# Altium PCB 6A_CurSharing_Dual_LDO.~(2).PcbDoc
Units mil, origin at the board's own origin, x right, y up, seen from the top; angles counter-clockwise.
Board outline 3000 x 2000 mil, 4 copper layers (Top Layer, MidLayer1, MidLayer2, Bottom Layer), stack 90 mil thick; 43 components, 16 nets, 118 pads, 82 vias.
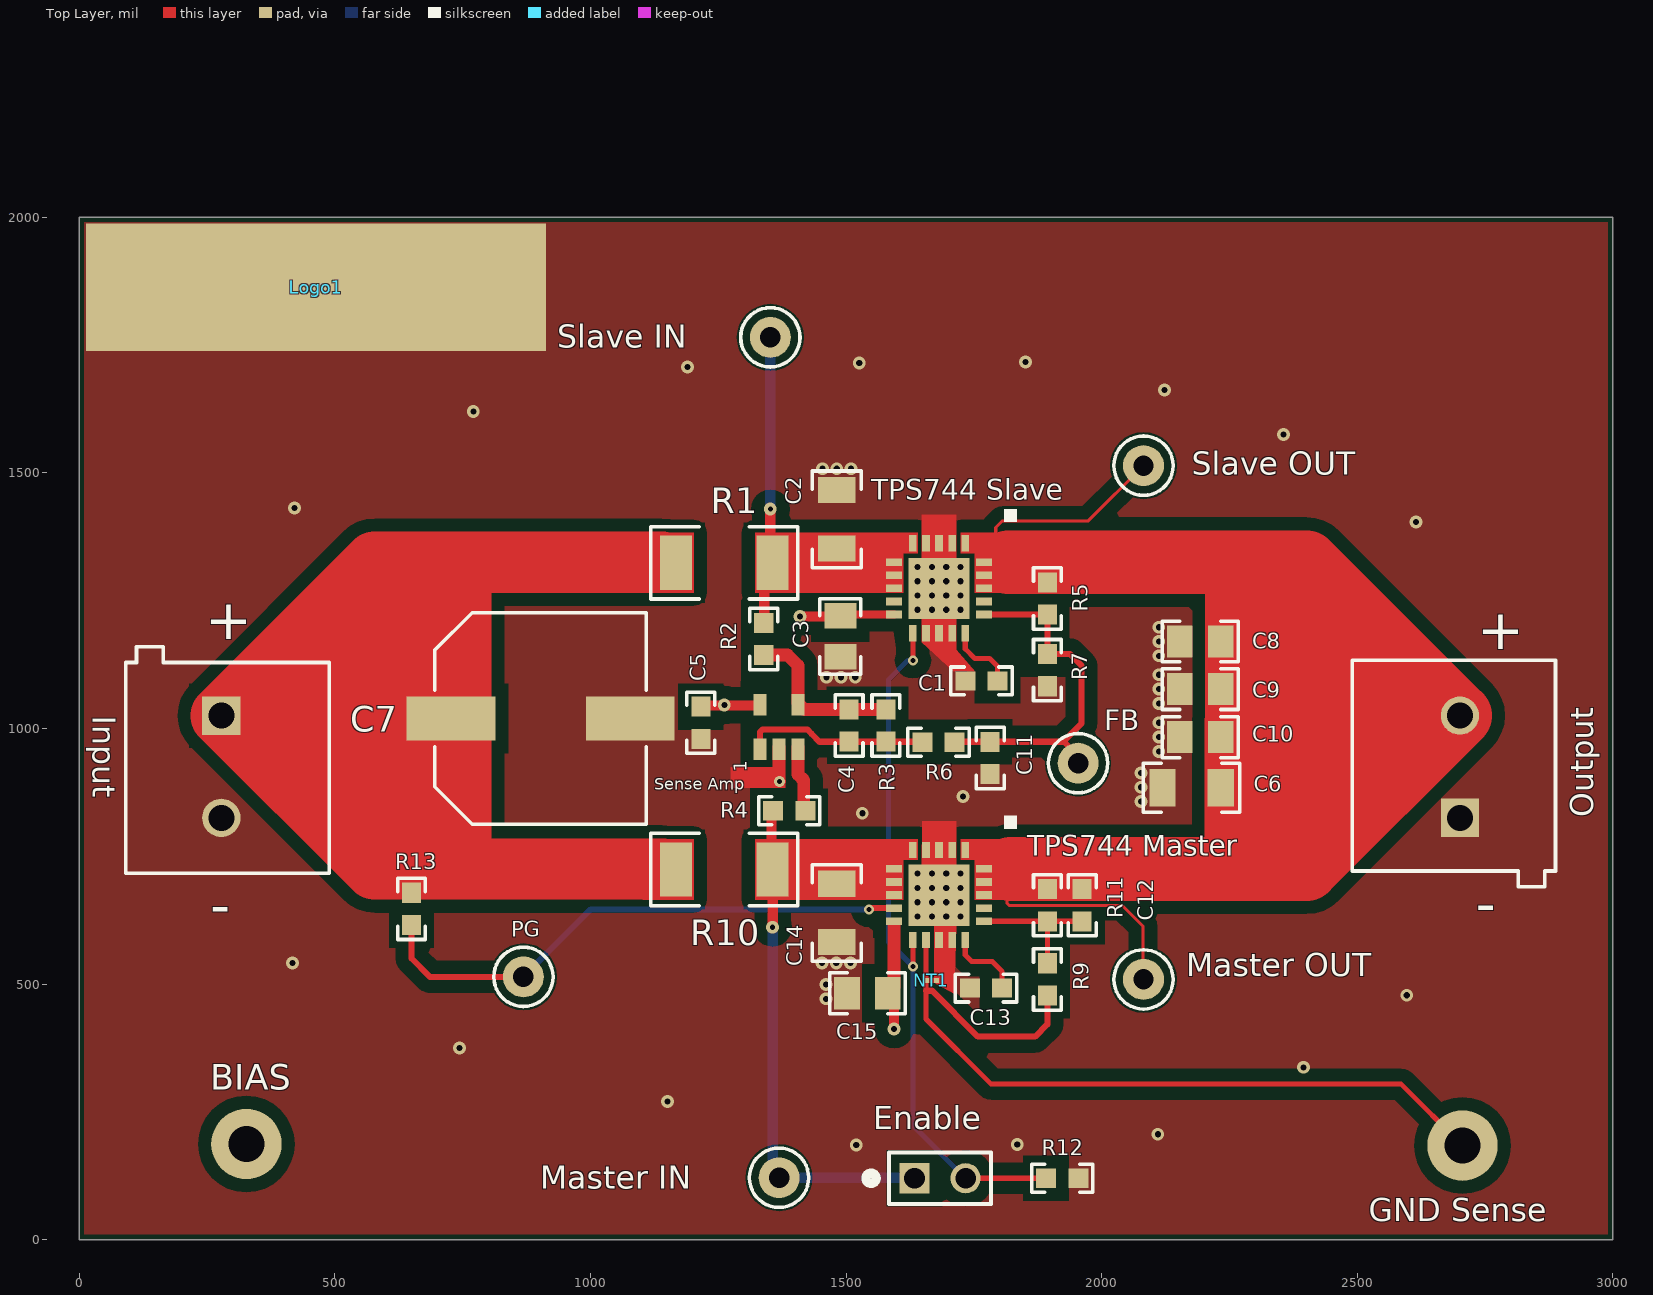
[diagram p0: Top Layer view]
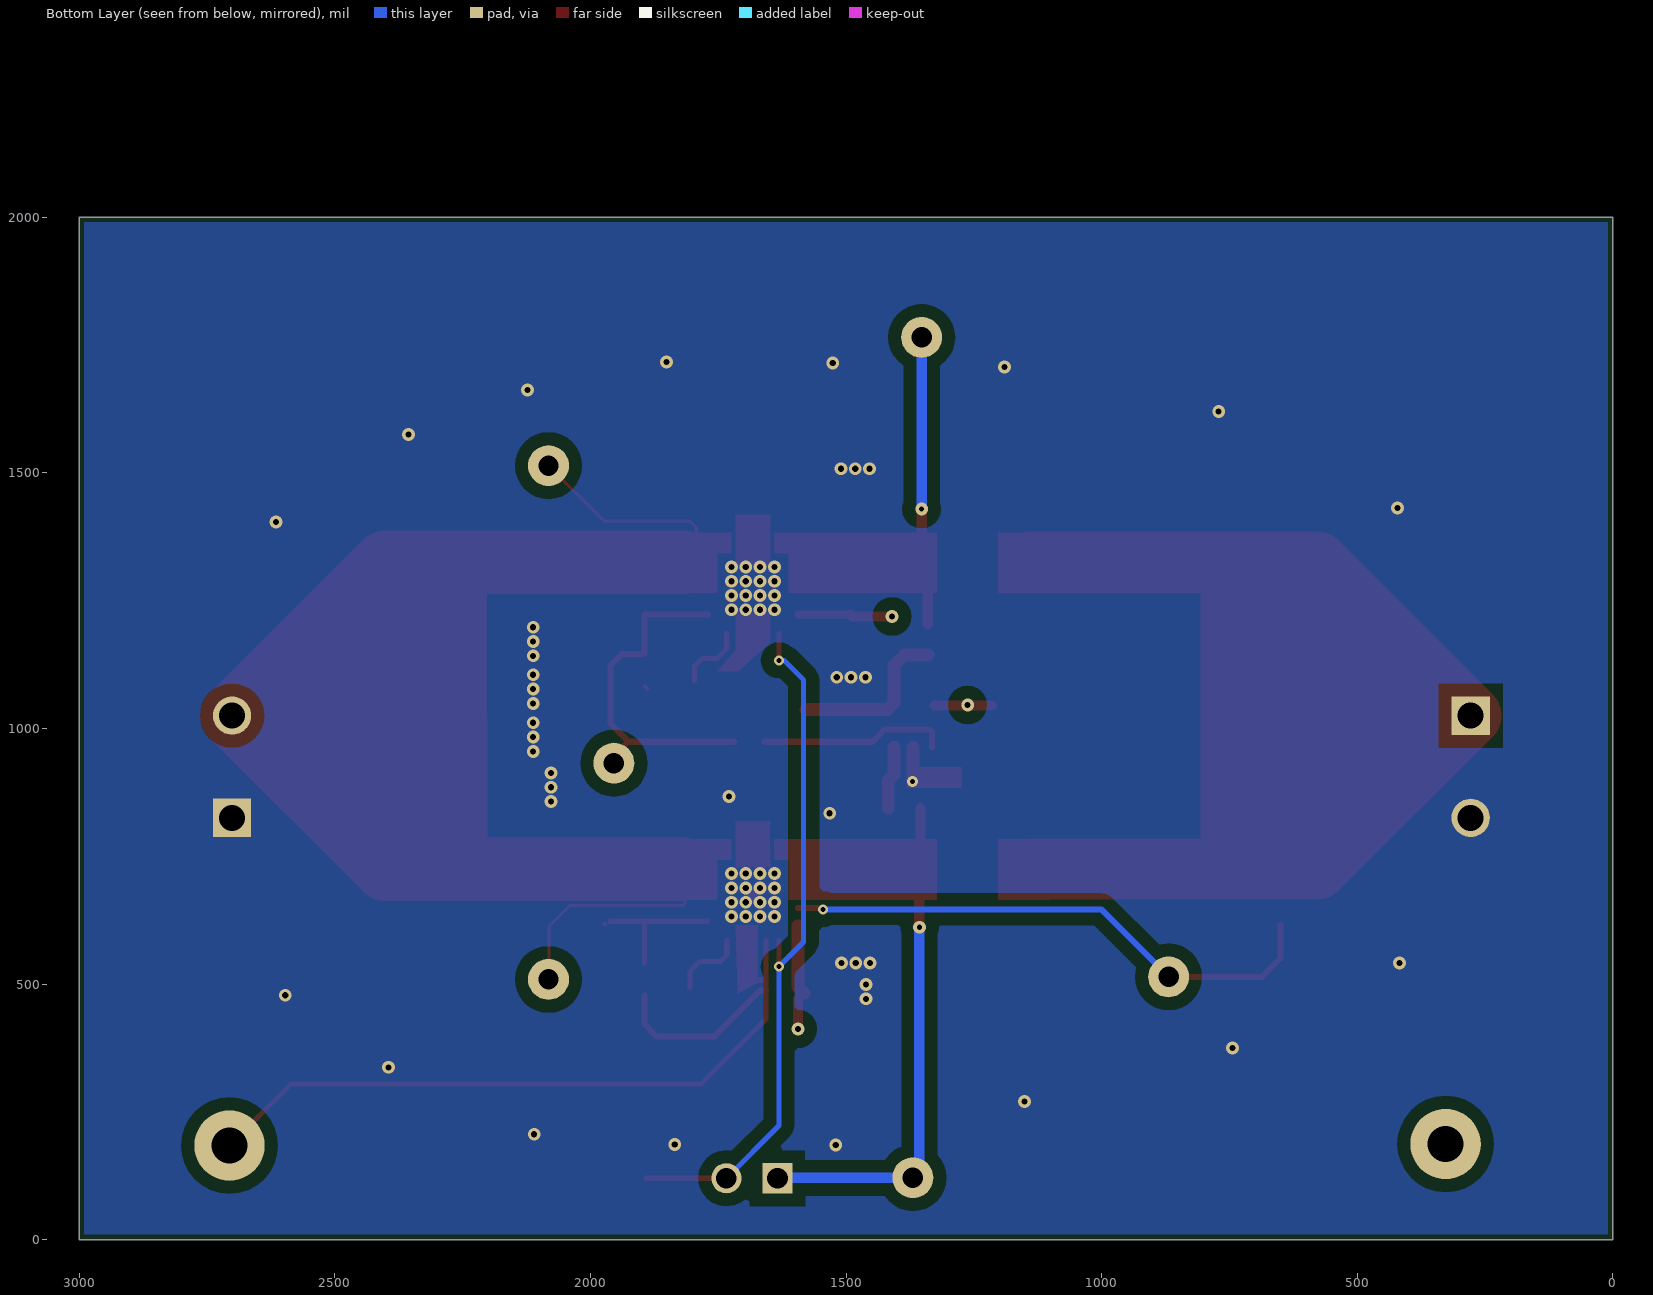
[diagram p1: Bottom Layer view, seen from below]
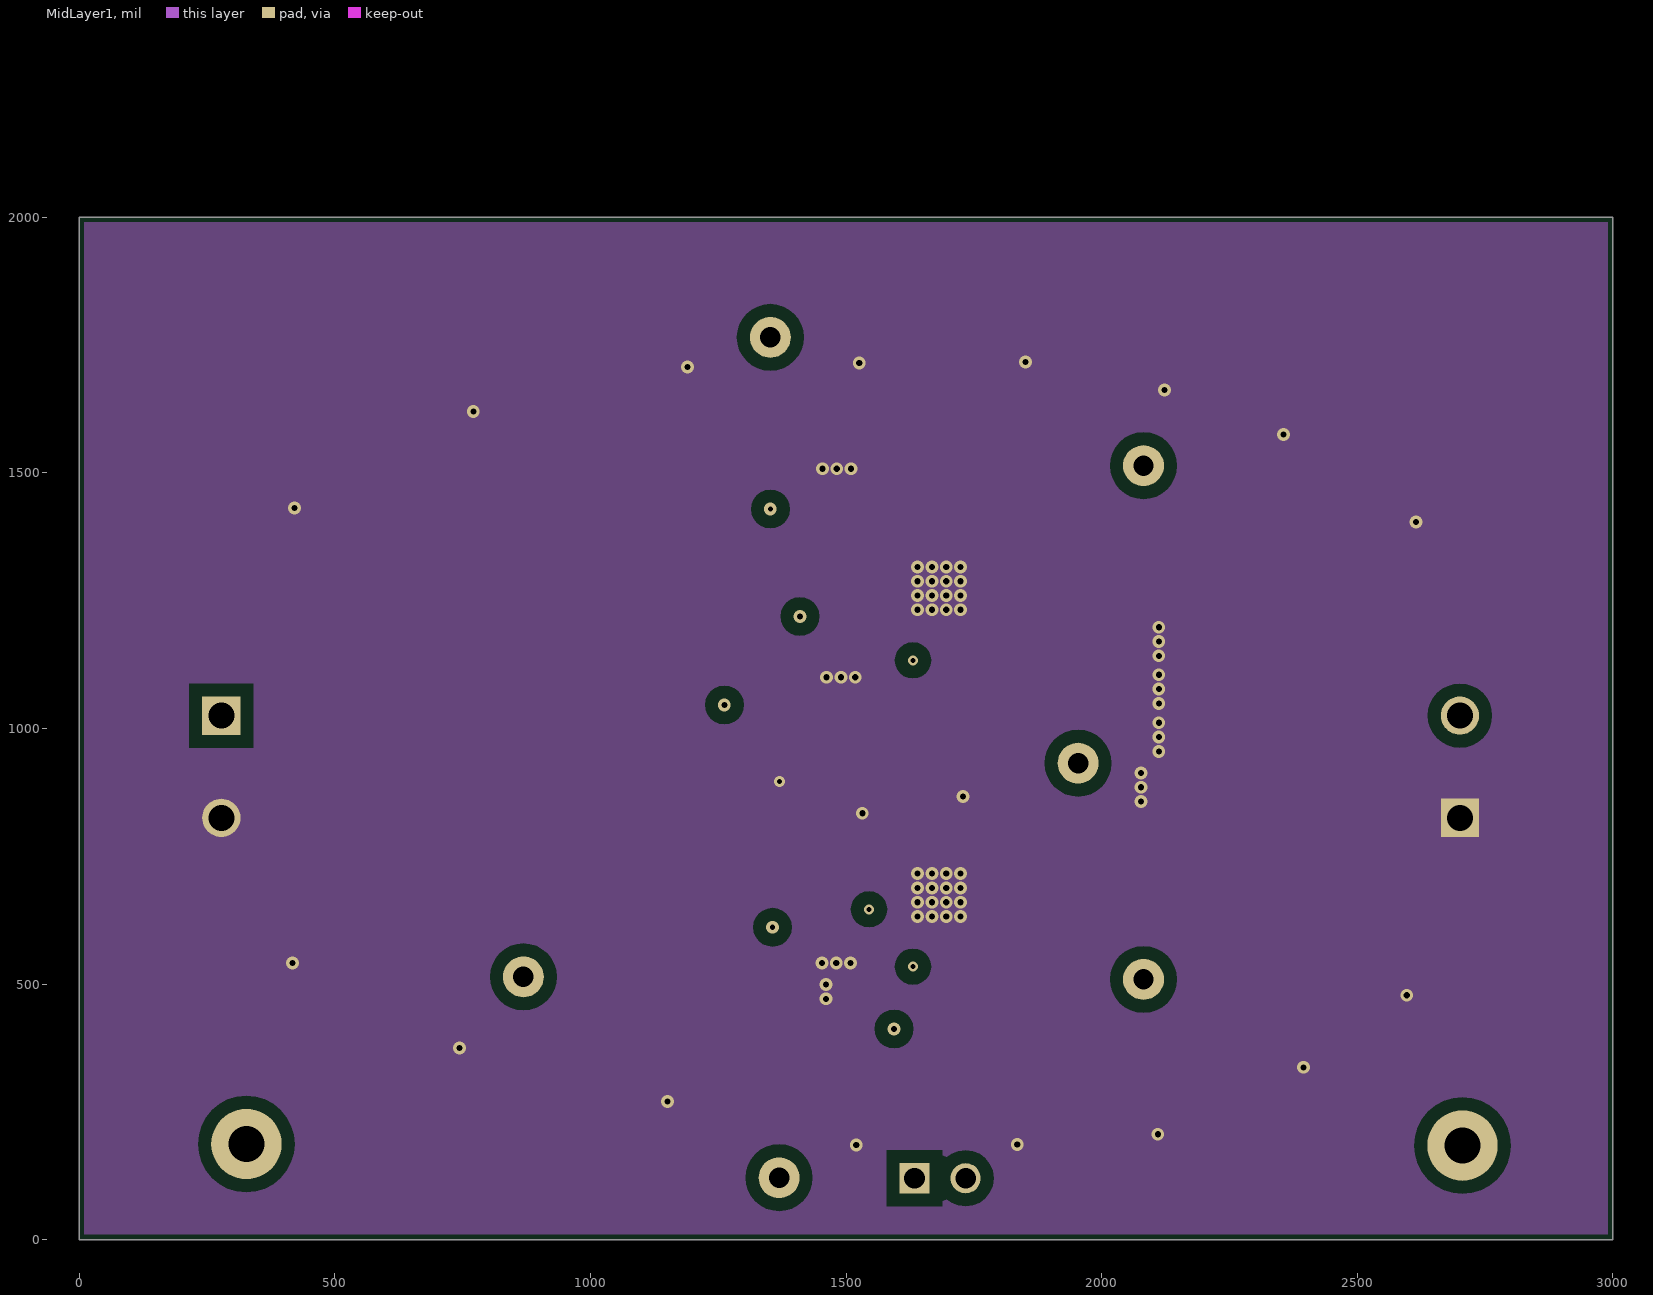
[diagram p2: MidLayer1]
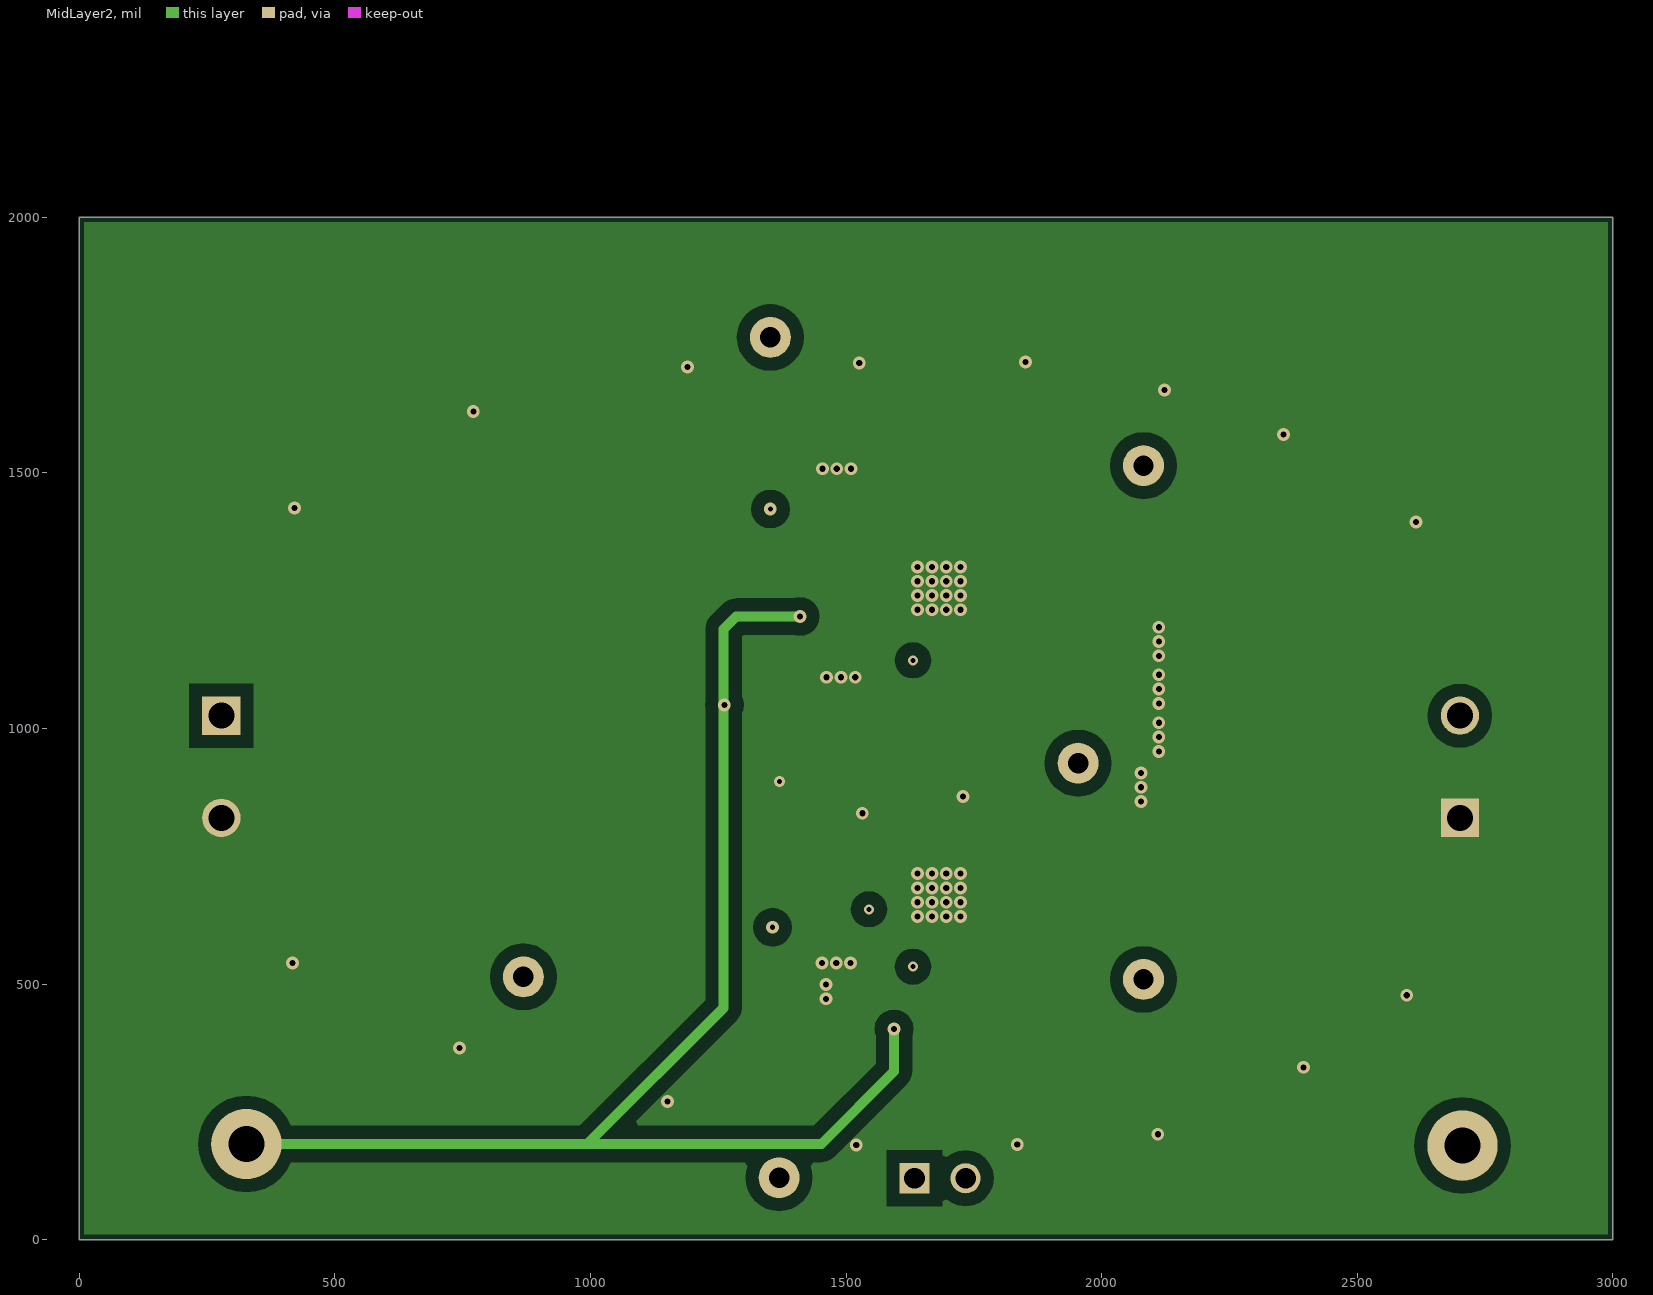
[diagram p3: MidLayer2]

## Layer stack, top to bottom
Top Layer: signal copper 1.4
Dielectric: core 59.2, FR-4, Dk 4.8
MidLayer1: signal copper 1.4
Dielectric: prepreg 12.6, FR-4, Dk 4.8
MidLayer2: signal copper 1.4
Dielectric: core 12.6, FR-4, Dk 4.8
Bottom Layer: signal copper 1.4

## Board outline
0,0 3000,0 3000,2000 0,2000

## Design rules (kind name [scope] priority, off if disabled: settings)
AcuteAngle [All] p1: minimum=4.50000000000000E+0001 checktracksonly=FALSE
AssemblyTestPointUsage [All] p1: valid=2
Clearance Clearance_BoardEdge_MountingHoles [OnCopper and InComponentClass('Mounting Holes') vs IsKeepOut] p1: gap=40
Clearance Clearance_BoardEdge_Poly [OnCopper and InPoly vs IsKeepOut] p2: gap=25
Clearance Clearance_BoardEdge [OnCopper and Not InComponentClass('Logo') and not InComponentClass('FiducialMark') and not InRegion(1000,500,4000,800) and Not IsKeepout vs IsKeepOut] p3: gap=75
Clearance Clearance_Poly [InPolygon] p4: gap=25
Clearance [All] p5: gap=8
ComponentClearance ComponentClearance_Shunt [InComponentClass('Header') vs InComponentClass('Shunt')] p1: gap=0 collisioncheckmode=3 verticalgap=0 showdistances=FALSE
ComponentClearance ComponentClearance_Logo [InComponentClass('Logo')] p2: gap=50 collisioncheckmode=3 verticalgap=10 showdistances=FALSE
ComponentClearance ComponentClearance_ScrewToNut [(HasFootprint('NY PMS 440 0025 PH')) vs (HasFootprint('Keystone_1902C'))] p3: gap=5 collisioncheckmode=3 verticalgap=10 showdistances=FALSE
ComponentClearance ComponentClearance_MountingHoles [InComponentClass('Mounting Holes')] p4: gap=250 collisioncheckmode=3 verticalgap=100000 showdistances=FALSE
ComponentClearance ComponentClearance_SmallPassives [HasFootprint('0201*') or HasFootprint('0402*') or HasFootprint('0508') or HasFootprint('0603*') or HasFootprint('0612') or HasFootprint('0805*') or HasFootprint('0815*') or HasFootprint('0830*') or HasFootprint('1206*') or HasFootprint('1210*') or HasFootprint('1808*') or HasFootprint('1812*') or HasFootprint('1825*') or HasFootprint('2010*') or HasFootprint('2220*') or HasFootprint('2225*') or HasFootprint('2512*') or HasFootprint('2728*') or HasFootprint('3518*') vs HasFootprint('0201*') or HasFootprint('0402*') or HasFootprint('0508') or HasFootprint('0603*') or HasFootprint('0612') or HasFootprint('0805*') or HasFootprint('0815*') or HasFootprint('0830*') or HasFootprint('1206*') or HasFootprint('1210*') or HasFootprint('1808*') or HasFootprint('1812*') or HasFootprint('1825*') or HasFootprint('2010*') or HasFootprint('2220*') or HasFootprint('2225*') or HasFootprint('2512*') or HasFootprint('2728*') or HasFootprint('3518*')] p5: gap=20 collisioncheckmode=3 verticalgap=10 showdistances=FALSE
ComponentClearance ComponentClearance_THtoSMT [IsThruComponent vs IsSMTComponent] p6: gap=100 collisioncheckmode=3 verticalgap=30 showdistances=FALSE
ComponentClearance ComponentClearance_THtoTH [IsThruComponent vs IsThruComponent] p7: gap=118.11 collisioncheckmode=3 verticalgap=30 showdistances=FALSE
ComponentClearance [All] p8: gap=40 collisioncheckmode=3 verticalgap=10 showdistances=FALSE
DiffPairsRouting [All] p1: maxlimit=100 minlimit=10 mostfreqgap=10 maxuncoupledlength=1000
FabricationTestPointUsage TestPointUsage [All] p1: valid=2 allowmultiple=FALSE
FabricationTestpoint Testpoint [All] p1: side=3 testpointundercomponent=TRUE minsize=40 maxsize=100 preferedsize=60 minholesize=0 maxholesize=40 preferedholesize=32 testpointgrid=1 allowsidetop=TRUE allowsidebottom=TRUE usegrid=TRUE gridtolerance=0.01
FanoutControl Fanout_LCC [IsLCC] p1: bgadir=Out bgaviamode=Centered fanoutstyle=Auto fanoutdirection=Alternating viagrid=1 // Fanout_LCC (Default Rule)
FanoutControl Fanout_BGA [IsBGA] p2: bgadir=Out bgaviamode=Centered fanoutstyle=Auto fanoutdirection=Alternating viagrid=1 // Fanout_BGA (Default Rule)
FanoutControl Fanout_Default [All] p4: bgadir=Out bgaviamode=Centered fanoutstyle=Auto fanoutdirection=Alternating viagrid=1 // Fanout_Default (Default Rule)
FanoutControl Fanout_Small [(CompPinCount < 5)] p5: bgadir=Out bgaviamode=Centered fanoutstyle=Auto fanoutdirection=OutThenIn viagrid=1 // Fanout_Small (Default Rule)
HoleSize [All] p1: absolutevalues=TRUE maxlimit=251 minlimit=8 maxpercent=80.000 minpercent=20.000
MinimumAnnularRing MinimumAnnularRing_ThermalPadVias [IsVia and InAnyComponent] p1: minimumring=5.91
MinimumAnnularRing [All] p2: minimumring=5
MinimumSolderMaskSliver MinimumSolderMaskSliver_Logo [InComponentClass('Logo') vs InComponentClass('Logo')] p1: minsoldermaskwidth=0.7
MinimumSolderMaskSliver [All] p2: minsoldermaskwidth=1.5
PlaneClearance [All] p1: clearance=5
PlaneConnect [All] p1: planeconnectstyle=Direct reliefexpansion=10 reliefentries=4 reliefconductorwidth=10 reliefairgap=10
PolygonConnect [All] p1: connectstyle=Direct reliefconductorwidth=10 reliefentries=4 polygonreliefangle="90 Angle" airgapwidth=10
RoutingVias ThermalPadVias [IsVia and InAnyComponent] p1: holewidth=7.87 width=19.68 viastyle="Through Hole" minholewidth=7.87 minwidth=19.68 maxholewidth=12.99 maxwidth=23.62
RoutingVias [All] p2: holewidth=16 width=34 viastyle="Through Hole" minholewidth=7.87 minwidth=20 maxholewidth=40 maxwidth=65
SMDToCorner [All] p1: distance=30000
SilkToSilkClearance [All] p1: silktosilkclearance=5
SilkscreenOverComponentPads [All] p1: minsilkscreentomaskgap=5
SolderMaskExpansion [All] p1: expansion=1.97
Width [All] p1: maxlimit=150 minlimit=6 preferedwidth=10 checkconnectedcopper=TRUE
13 further rules are at their usual default settings.

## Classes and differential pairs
component class Logo: Logo1

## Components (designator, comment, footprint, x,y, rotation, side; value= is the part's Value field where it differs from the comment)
BIAS "Suggest using a net name here" Keystone_1562-2#1 327,186 r0 top
C1 "GRM188R71E103KA01D" 0603 1765,1093 r180 top
C2 "C3216X5R1A106M" 1206 1482,1409 r90 top
C3 "GRM21BR71C105KA01L" 0805_HV 1489,1180 r270 top
C4 "N" 0603 1506,1005.67 r90 top
C5 "GRM188R61C104KA01D" 0603 1216,1011 r270 top
C6 "GRM31CR60J107ME39L" 1206 2176,884 r180 top
C7 "APXA100ARA331MJ80G" CAPSMT_62_J80 902,1019 r0 top
C8 "GRM21BR71C105KA01L" 0805_HV 2193,1170 r180 top
C9 "GRM21BR71C105KA01L" 0805_HV 2193,983 r180 top
C10 "GRM21BR71C105KA01L" 0805_HV 2193,1077 r180 top
C11 "06033C101KAT2A" 0603 1782,942 r270 top
C12 "06033C101KAT2A" 0603 1962,654 r270 top
C13 "GRM188R71E103KA01D" 0603 1774,492 r180 top
C14 "C3216X5R1A106M" 1206 1482,639 r270 top
C15 "GRM21BR71C105KA01L" 0805_HV 1542,482 r180 top
Enable "5-146261-1" CONN_5-146261-1 1684,120 r0 top
FB "5003" Keystone5003 1954,932 r0 top
"GND Sense" "Suggest using a net name here" Keystone_1562-2#2 2706,184 r90 top
Input "1715721" PhoenixContact_1715721 278,925 r270 top
Logo1 "Texas Instruments" TI_Stacked_SolderMask_Small 460,1860 r0 top
"Master IN" "5003" Keystone5003 1369,121 r90 top
"Master OUT" "5003" Keystone5003 2082,509 r90 top
NT1 "Net-Tie" Net-Tie_10mil 1667,507 r0 top net-tie
Output "1715721" PhoenixContact_1715721 2701,925 r90 top
PG "5003" Keystone5003 869,514 r0 top
R1 "LVK20R030FER" 2010M 1262,1324 r0 top
R2 "RC0603JR-0710KL" 0603 1339,1175 r90 top
R3 "CRCW06030000Z0EA" 0603 1578,1005.67 r270 top
R4 "RC0603JR-0710KL" 0603 1389,839 r0 top
R5 "RC0603FR-073K57L" 0603 1894,1254 r90 top
R6 "RC0603FR-0715KL" 0603 1681,973 r0 top
R7 "CRCW06031K15FKEA" 0603 1894,1114 r90 top
R9 "RC0603FR-073K57L" 0603 1894,654 r90 top
R10 "LVK20R030FER" 2010M 1262,724 r0 top
R11 "CRCW06031K15FKEA" 0603 1894,509 r90 top
R12 "RC0603JR-0730KL" 0603 1923,120 r180 top
R13 "RC0603JR-0730KL" 0603 650,647 r90 top
"Sense Amp" "OPA333AIDBV" SOT23-5P 1369,1004 r90 top
"Slave IN" "5003" Keystone5003 1352,1765 r90 top
"Slave OUT" "5003" Keystone5003 2082,1514 r90 top
"TPS744 Master" "TPS744XXRGW" RGW20 1682,674 r270 top
"TPS744 Slave" "TPS744XXRGW" RGW20 1682,1274 r270 top

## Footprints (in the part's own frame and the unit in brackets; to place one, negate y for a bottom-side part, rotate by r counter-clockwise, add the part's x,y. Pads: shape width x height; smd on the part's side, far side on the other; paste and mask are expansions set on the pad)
0603 [mm] "0603 from SM-752 data"
  rect 1x0.95 smd: 1(-0.8,0) 2(0.8,0)
  silkscreen extent -1.52,-0.69 1.52,0.69, body extent -0.87,-0.47 0.87,0.47, height 0.85
0805_HV [mil] "0805 with 30mil clearance between pads"
  rect 50x63 smd: 1(-40,0) 2(40,0)
  silkscreen extent -74,-40 74,40, body extent -43,-29 43,29, height 43
1206 [mm] "1206 from SM-752 data"
  rect 1.3x1.85 smd: 1(-1.45,0) 2(1.45,0)
  silkscreen extent -2.4,-1.21 2.4,1.21, body extent -1.7,-0.9 1.7,0.9, height 1.35
2010M [mm]
  rect 1.6x2.7 smd: 1(-2.4,0) 2(2.4,0)
  silkscreen extent -3.65,-1.8 3.65,1.8, body extent -2.73,-1.45 2.73,1.45, height 1.66
CAPSMT_62_J80 [mm] "10 x 7.7mm:  Chemi-Con J80"
  rect 4.4x2.2 smd: 1(-4.438,0.012) 2(4.462,0.012)
  silkscreen extent -5.24,-5.24 5.26,5.26, body extent -5.25,-5.25 5.27,5.27, height 8
CONN_5-146261-1 [mm] "Sullins"
  rect 1.5x1.5 hole 1.02: 1(-1.27,0)
  round 1.5 hole 1.02: 2(1.27,0)
  silkscreen extent -3.68,-1.27 2.54,1.27, body extent -2.51,-1.27 2.51,1.27, height 10.87
Keystone5003 [mil] "For Keystone 500x miniature loop terminals"
  round 80 hole 40: 1(0,0)
  silkscreen extent -58,-58 58,58, body extent -49,-49 49,49, height 182
Keystone_1562-2#1 [mm] "Keystone Electronics Turret"
  round 3.5 hole 1.8: 1(0,0.025)
  body extent -1.6,-1.6 1.59,1.59, height 4
Keystone_1562-2#2 [mm] "Keystone Electronics Turret"
  round 3.5 hole 1.8: 1(0,0)
  body extent -1.6,-1.6 1.59,1.59, height 4
Net-Tie_10mil [mil] "10mil net tie, no solder mask opening, no solder paste"
  rect 10x10 smd paste-5 mask-5: 1(-10,0) 2(10,0)
  Top Layer region: -6,5 6,5 6,-5 -6,-5
PhoenixContact_1715721 [mm] "Phoenix Contact 1715721 used on LM3445 design from Longmont"
  rect 1.905x1.905 hole 1.3: 1(-2.54,0)
  round 1.9 hole 1.3: 2(2.54,0)
  silkscreen extent -5.97,-4.75 5.28,5.36, body extent -5.82,-4.6 5.08,5.2, height 14.2
RGW20 [mil]
  rect 32x15 smd mask+1: 1(-88,51.2) 2(-88,25.6) 3(-88,0) 4(-88,-25.6) 5(-88,-51.2) 11(88,-51.2) 12(88,-25.6) 13(88,0) 14(88,25.6) 15(88,51.2)
  rect 15x32 smd mask+1: 6(-51.2,-88.1) 7(-25.6,-88.1) 8(0,-88.1) 9(25.6,-88.1) 10(51.2,-88.1) 16(51.2,87.9) 17(25.6,87.9) 18(0,87.9) 19(-25.6,87.9) 20(-51.2,87.9)
  rect 120x120 smd: 21(0.15,-0.05)
  silkscreen extent -155,127 -130,152
SOT23-5P [mil]
  rect 42x25 smd: 1(-45,37) 2(-45,0) 3(-45,-37) 4(42,-37) 5(42,37)
TI_Stacked_SolderMask_Small [mil]
  rect 900x250 smd paste-125 mask-125: 0(3,3)

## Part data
BIAS "GND Sense": library part 1562-2, "Terminal, Turret, TH, Hollow, Single"
C1 C13: "CAP, CERM, 0.01uF, 25V, +/-10%, X7R, 0603"
C2 C14: "CAP, CERM, 10uF, 10V, +/-20%, X5R, 1206"
C3 C8 C9 C10 C15: "CAP, CERM, 1uF, 16V, +/-10%, X7R, 0805"
C4: library part 06033C101KAT2A, "CAP, CERM, 100pF, 25V, +/-10%, X7R, 0603"
C5: "CAP, CERM, 0.1uF, 16V, +/-10%, X5R, 0603"
C6: "CAP, CERM, 100uF, 6.3V, +/-20%, X5R, 1206"
C7: "CAP, AL, 330uF, 10V, +/-20%, 0.024 ohm, SMD"
C11 C12: "CAP, CERM, 100pF, 25V, +/-10%, X7R, 0603"
Enable: "Header, 100mil, 2x1, Gold plated, TH"
FB "Master IN" "Master OUT" PG "Slave IN" "Slave OUT": "Test Point, Miniature, Orange, TH"
Input Output: "Conn Term Block, 2POS, 5.08mm, TH"
Logo1: library part TI_Logo, "Texas Instrument Corporate Signature"
NT1: "Single point connection between nets."
R1 R10: "RES, 0.03 ohm, 1%, 0.75W, 2010"
R2 R4: "RES, 10k ohm, 5%, 0.1W, 0603"
R3: "RES, 0 ohm, 5%, 0.1W, 0603"
R5 R9: "RES, 3.57k ohm, 1%, 0.1W, 0603"
R6: "RES, 15.0k ohm, 1%, 0.1W, 0603"
R7 R11: "RES, 1.15k ohm, 1%, 0.1W, 0603"
R12 R13: "RES, 30k ohm, 5%, 0.1W, 0603"
"Sense Amp": "IC, 1.8V, microPower, CMOS Op Amp, Zerø-Drift Series"
"TPS744 Master" "TPS744 Slave": "IC, 1.5a LDO With Programmable Sequencing"

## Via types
v1: diameter 25, hole 12, Top Layer to Bottom Layer, 60 vias
v2: diameter 25, hole 12, Top Layer to Bottom Layer, tented both sides, 16 vias
v3: diameter 20, hole 10, Top Layer to Bottom Layer, 3 vias
v4: diameter 25, hole 10, Top Layer to Bottom Layer, 2 vias
v5: diameter 22, hole 10, Top Layer to Bottom Layer, 1 vias

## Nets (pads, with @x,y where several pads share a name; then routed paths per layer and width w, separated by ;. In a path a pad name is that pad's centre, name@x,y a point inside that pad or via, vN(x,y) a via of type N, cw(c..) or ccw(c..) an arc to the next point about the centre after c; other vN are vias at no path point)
BIAS: "Sense Amp.5" "TPS744 Master.10" "TPS744 Slave.10" BIAS.1 C3.1 C5.1 C15.1 | length 3195.7
  Top Layer w15: C3.1@1491.8,1222.8 1593.9,1222.8
  Top Layer w20: C5.1@1215,1045 1327,1045 ; v1(1410,1219) 1488,1219 C3.1 C3.1@1491.8,1222.8 ; C15.1 1594,470 v1(1594,412)
  Top Layer w25: C15.1 1593.9,493.9 1593.9,614
  MidLayer2 w20: BIAS.1 1452,187 1594,329 v1(1594,412) ; 994,187 1260.5,453.5 1260.5,1194.5 1285,1219 v1(1410,1219)
  other v1: 1262,1046
"EN MASTER": "TPS744 Master.11" "TPS744 Slave.11" Enable.2 R12.2 | length 1355.4
  Top Layer w10: 1630,1185.2 1631,1184.2 ; 1630.8,586 1631,585.8 v3(1631,534) ; 1630.8,1186 1631,1185.8 1631,1184.2 ; v3(1631,1133) 1631,1184.2 ; Enable.2 R12.2
  Bottom Layer w10: v3@1621,1133 1583,1095 1583,582 v3(1631,534) 1631,223 Enable.2
GND: "Sense Amp.2" "TPS744 Master.2" "TPS744 Master.3" "TPS744 Master.4" "TPS744 Master.13" "TPS744 Master.14" "TPS744 Master.21" "TPS744 Slave.2" "TPS744 Slave.3" "TPS744 Slave.4" "TPS744 Slave.12" "TPS744 Slave.13" "TPS744 Slave.14" "TPS744 Slave.21" C1.2 C2.2 C3.2 C5.2 C6.2 C7.2 C8.2 C9.2 C10.2 C11.2 C13.2 C14.2 C15.2 Input.2 Logo1.0 NT1.2 Output.1 R7.1 R12.1 | length 80.9
  Top Layer w8: R7.1@1888.31,1076.81 R7.1
  Top Layer w25: 1369,963 1369,903 1368,902 1368,896 v5(1370,896) ; 1681.95,673.85 1684.4,671.4
  other v1: 1461,471 1461,499 1453,541 1481,541 1509,541 1640,632 1668,632 1696,632 1724,632 1640,660 1668,660 1696,660 1724,660 1640,688 1668,688 1696,688 1724,688 1640,716 1668,716 1696,716 1724,716 1532,834 2077,857 1729,867 2077,885 2077,913 2112,955 2112,983 2112,1011 2112,1049 2112,1077 1462,1100 1490,1100 1518,1100 2112,1105 2112,1142 2112,1170 2112,1198 1640,1232 1668,1232 1696,1232 1724,1232 1640,1260 1668,1260 1696,1260 1724,1260 1640,1288 1668,1288 1696,1288 1724,1288 1640,1316 1668,1316 1696,1316 1724,1316 1454,1508 1482,1508 1510,1508
  other v2: 1520,185 1835,186 2110,206 1151,270 2395,337 744,375 2597,478 417,541 2615,1404 421,1431 2356,1575 771,1620 2123,1662 1190,1707 1526,1715 1851,1717
"IN MASTER": "Master IN.1" "TPS744 Master.5" "TPS744 Master.6" "TPS744 Master.7" "TPS744 Master.8" C14.1 Enable.1 R4.1 R10.2 | length 994.4
  Top Layer w20: R4.1@1354.5,844 1354.5,725.98 R10.2 v4(1356.49,611)
  Bottom Layer w20: v4(1356.49,611) 1356.49,133.51 1369,121 1633,121 Enable.1
"IN SLAVE": "Slave IN.1" "TPS744 Slave.5" "TPS744 Slave.6" "TPS744 Slave.7" "TPS744 Slave.8" C2.1 R1.2 R2.2 | length 563.8
  Top Layer w20: R2.2@1340,1203.5 1340,1307.51 R1.2 ; R1.2@1352,1328.49 v4(1352,1429)
  Bottom Layer w20: v4(1352,1429) 1352,1765
INPUT: C7.1 Input.1 R1.1 R10.1 R13.2 | length 1973.5
  Top Layer w120: R1.1@1140,1325 578,1325 Input.1 578,725 R10.1@1141,725
NetC1_1: "TPS744 Slave.15" C1.1 | length 136.2
  Top Layer w10: 1733.2,1186 1733.2,1155.8 1752,1137 1781,1137 1796.5,1121.5 C1.1
NetC4_1: "Sense Amp.1" C4.1 R3.2 R6.1 | length 370.5
  Top Layer w10: C4.1 1506.18,974 C4.1@1506.55,973.62
  Top Layer w12: 1332,963 1332,993 1337,998 1424.3,998 1432.5,989.8 1432.5,989.5 1448,974 1506.18,974 R6.1@1659.5,974
NetC4_2: "Sense Amp.4" C4.2 R2.1 R3.1 | length 325.8
  Top Layer w25: R2.1 1385.5,1143.5 1406,1123 1406,1050 1418.83,1037.17 R3.1
NetC11_1: "TPS744 Slave.16" C11.1 FB.1 R5.1 R6.2 R7.2 | length 701.9
  Top Layer w12: R6.2@1718.5,974 1925,974 1961,1010 1961,1123 1938.5,1145.5 R7.2 R5.1 ; 1769.9,1222.8 R5.1@1893.8,1222.8 ; 1925.5,974.5 1954,945.99 FB.1
NetC12_2: "TPS744 Master.16" C12.2 R9.1 R11.2 | length 274.4
  Top Layer w10: 1769.9,622.8 1961.7,622.8 C12.2 ; R11.2 R9.1 ; C12.2@1971.87,617.04 C12.2@1972,617.18
NetC13_1: "TPS744 Master.15" C13.1 | length 147.4
  Top Layer w10: 1733.2,586 1733.2,556.8 1746,544 1786,544 1805.5,524.5 C13.1
"NetGND Sense_1": "GND Sense.1" "TPS744 Master.12" NT1.1 R11.1 | length 1647.8
  Top Layer w10: 1656.4,586 1656.4,486.8 1656.4,431.6 1784,304 2586,304 2706,184
  Top Layer w12: 1656.4,486.8 1668.4,486.8 1758.2,397 1870,397 1894,421 R11.1
NetPG_1: "TPS744 Master.9" PG.1 R13.1 | length 1080
  Top Layer w12: R13.1 650,550 686,514 PG.1 ; v3(1545,646) 1547.4,648.4 1593.9,648.4
  Bottom Layer w12: PG.1 1001,646 v3(1545,646)
NetR4_2: "Sense Amp.3" R4.2 | length 123.8
  Top Layer w25: 1406,963 1406,910 1417.5,898.5 R4.2@1417.5,844
OUTPUT: "Master OUT.1" "Slave OUT.1" "TPS744 Master.1" "TPS744 Master.18" "TPS744 Master.19" "TPS744 Master.20" "TPS744 Slave.1" "TPS744 Slave.18" "TPS744 Slave.19" "TPS744 Slave.20" C6.1 C8.1 C9.1 C10.1 C12.1 Output.2 R5.2 R9.2 | length 2915.4
  Top Layer w6: 1815,724 1815,658 1819.81,653.19 2040.81,653.19 2081,613 2081,475 ; 1815,1324 1793,1346 1793,1393 1806,1406 1974,1406 2082,1514
  Top Layer w125: 1818,1325 2401,1325 Output.2 2401,725 1823,725
pads on no net: "TPS744 Master.17" "TPS744 Slave.9" "TPS744 Slave.17"

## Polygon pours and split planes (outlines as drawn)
GND on MidLayer1 "MidLayer1-No Net" (solid, pour order 3): 10,1990 10,10 2990,10 2990,1990 10,1990
GND on MidLayer2 "MidLayer2-No Net" (solid, pour order 5): 10,1990 10,10 2990,10 2990,1990 10,1990
GND on Bottom Layer "Bottom Layer-No Net" (solid, pour order 7): 10,1990 10,10 2990,10 2990,1990 10,1990
GND on Top Layer "Top Layer-No Net" (solid, remove dead copper, pour order 6): 10,1990 10,10 2990,10 2990,1990 10,1990

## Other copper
Top Layer:
  region net GND: 1381,884 1381,924 1275,924 1275,884
  region net GND: 1716,1418 1716,1320 1715,1319 1648,1319 1648,1418
  region net GND: 1716,1224 1716,1154 1753,1111 1710,1112 1648,1169 1648,1224
  region net GND: 1673,615 1716,615 1712,481 1673,502
  region net GND: 1716,818 1716,729 1715,728 1648,728 1649,818
  region net INPUT: 1202,783 1202,665 1102,665 1102,783
  region net INPUT: 1202,1383 1202,1265 1102,1265 1102,1383
  region net "IN SLAVE": 1322,1383 1640,1383 1640,1343 1612,1343 1612,1265 1322,1265
  region net "IN MASTER": 1322,783 1640,783 1640,743 1612,743 1612,665 1322,665
  region net OUTPUT: 2042,1383 1724,1383 1724,1343 1752,1343 1752,1265 2042,1265
  region net OUTPUT: 2042,783 1724,783 1724,743 1752,743 1752,665 2042,665
  region net OUTPUT: 2202,714 2332,714 2650,1027 2355,1325 2203,1328
  region net INPUT: 806,714 595,714 296.5,1021.5 594,1328 806,1328

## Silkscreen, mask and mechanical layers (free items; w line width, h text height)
Top Overlay:
  text "+" at 247,1174 h80
  text "+" at 2735,1155 h80
  text "-" at 2732,619 h80
  text "-" at 256,616 h80
Top Solder:
  text "Dual TPS744 6A Low Noise LDO" at 1603,1921 h50
M1 Board Outline:
  the board outline again, w7
M9 Title Sheet:
  drawing of 57 lines, arcs and shapes, not listed
  text "1" at -58.66,7147 h70
  text "2" at 2437,7147 h70
  text "3" at 4926.34,7147 h70
  text "4" at 7433.01,7147 h70
  text "5" at 9932,7147 h70
  text "6" at 12437,7147 h70
  text "A" at -1215,6004 h70
  text "A" at 13585,6004 h70
  text "B" at -1215,3624 h70
  text "B" at 13585,3624 h70
  text "C" at -1215,1249 h70
  text "C" at 13585,1249 h70
  text "PROJECT TITLE:" at 10545,-612 h45
  text ".PRJ_Title" at 10595,-745.33 h70
  text "DESIGNED FOR:" at 10545,-913 h45
  text ".PRJ_Customer" at 10595,-1053 h70
  text "D" at -1215,-1121 h70
  text "D" at 13585,-1121 h70
  text "FILE NAME:" at 10545,-1213 h45
  text ".PCB_File_Name_No_Path" at 10595,-1333 h70
  text "Texas Instruments (TI) and/or its licensors do not warrant the accuracy or completeness of this specification" at 5575.5,-1494.84 h45
  text "ENGINEER:" at 10545,-1503 h45
  text "LAYOUT BY:" at 12050,-1503 h45
  text "or any information contained therein. TI and/or its licensors do not warrant that this design will meet" at 5530.51,-1607.5 h45
  text ".PRJ_Engineer" at 10574.5,-1648 h70
  text ".PCB_Layout" at 12080,-1648 h70
  text "the specifications, will be suitable for your application or fit for any particular purpose, or will operate in" at 5530.51,-1720.17 h45
  text ".Layer_Name" at -221.5,-1747.99 h60
  text "ALTIUM DESIGNER VERSION:" at 12050,-1813 h45
  text "an implementation. TI and/or its licensors do not warrant that the design is production worthy. You should" at 5530.51,-1832.83 h45
  text "completely validate and test your design implementation to confirm the system functionality for your application." at 5575.5,-1945.5 h45
  text ".print_Scale" at 10595,-1946.33 h70
  text ".Application_BuildNumber" at 12100.5,-1946.33 h70
  text "1" at -58.66,-2153 h70
  text "2" at 2437,-2153 h70
  text "3" at 4926.34,-2153 h70
  text "4" at 7433.01,-2153 h70
  text "5" at 9932,-2153 h70
  text "6" at 12437,-2153 h70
